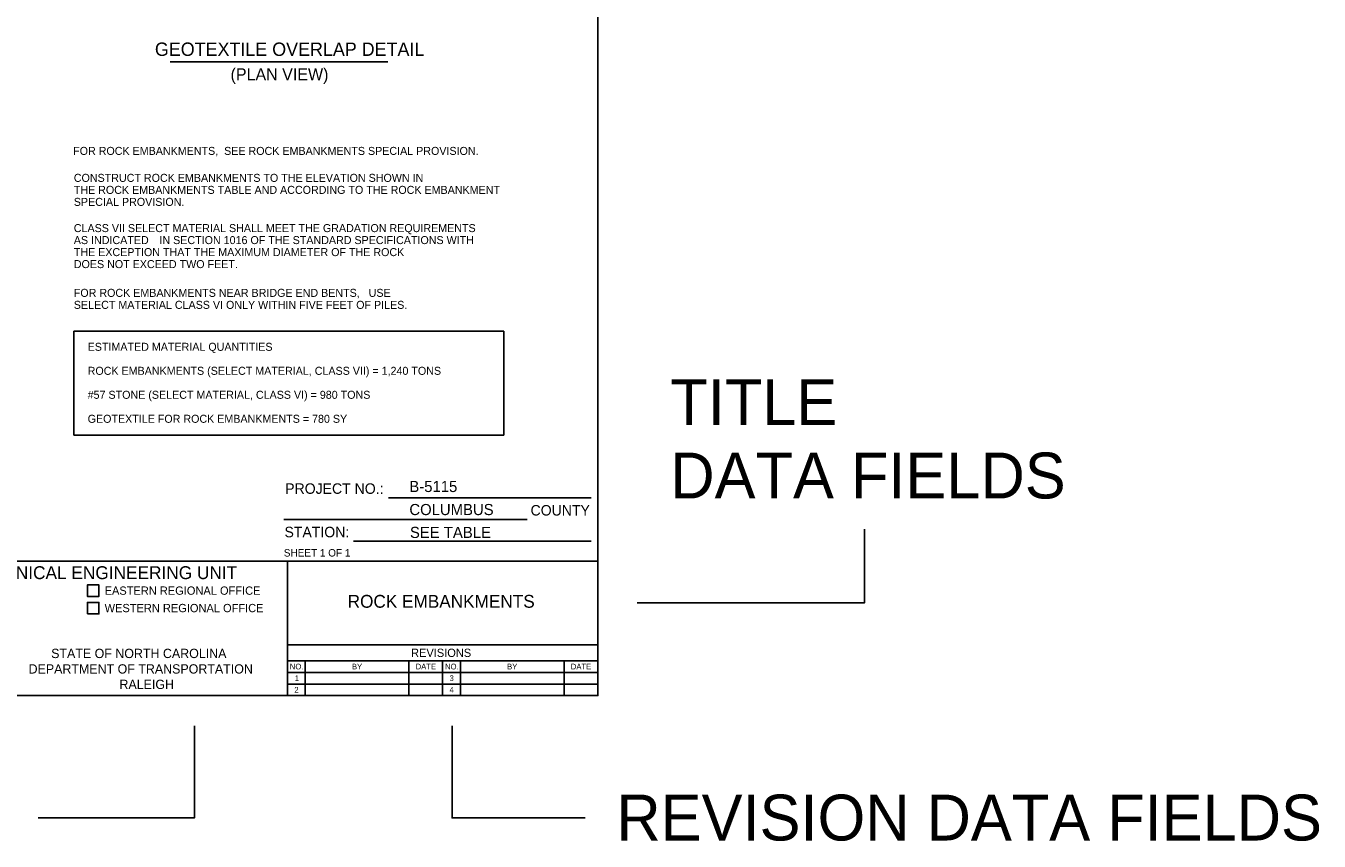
# Model space of a CAD drawing. Extents: x 2189223 to 2190097, y 563994 to 564498.
# Drawn here: x 2189702.6 to 2190097.3, y 563994.5 to 564243.4 of the extents above; entities that cross this region are included whole.
import ezdxf

# ---------------------------------------------------------------- set-up
doc = ezdxf.new("R2010")
doc.units = 0
for name, color, linetype in [('Default', 7, 'Continuous'), ('Geotech Sheets and Borders Cell', 7, 'Continuous'), ('Old_Level_2', 7, 'Continuous'), ('Old_Level_37', 7, 'Continuous')]:
    doc.layers.add(name, color=color, linetype=linetype)

msp = doc.modelspace()

# ---------------------------------------------------------------- linework, layer by layer
at = {"layer": 'Default'}
for points in [[(2189347.77, 564405.93), (2189877.15, 564405.93), (2189877.15, 564038.89), (2189347.77, 564038.89)], [(2189717.21, 564150.14), (2189848.44, 564150.14), (2189848.44, 564118.44), (2189717.21, 564118.44)]]:
    msp.add_lwpolyline(points, close=True, dxfattribs=at)
at = {"layer": 'Geotech Sheets and Borders Cell'}
for p, q in [((2189813.25, 564099.27), (2189875.1, 564099.27)), ((2189781.29, 564092.64), (2189855.53, 564092.64)), ((2189802.59, 564086.01), (2189875.1, 564086.01))]:
    msp.add_line(p, q, dxfattribs=at)
for points in [[(2189958.56, 564089.71), (2189958.56, 564067.26), (2189889.2, 564067.26)], [(2189754.02, 564029.63), (2189754.02, 564001.54), (2189706.34, 564001.54)], [(2189832.65, 564029.63), (2189832.65, 564001.54), (2189873.23, 564001.54)]]:
    msp.add_lwpolyline(points, dxfattribs=at)
for points in [[(2189667.83, 564079.96), (2189782.41, 564079.96), (2189782.41, 564038.89), (2189667.83, 564038.89)], [(2189782.41, 564079.96), (2189877.15, 564079.96), (2189877.15, 564054.38), (2189782.41, 564054.38)], [(2189782.41, 564079.96), (2189877.15, 564079.96), (2189877.15, 564038.89), (2189782.41, 564038.89)], [(2189721.36, 564069.19), (2189724.86, 564069.19), (2189724.86, 564072.69), (2189721.36, 564072.69)], [(2189721.36, 564063.85), (2189724.86, 564063.85), (2189724.86, 564067.35), (2189721.36, 564067.35)], [(2189782.41, 564054.38), (2189877.15, 564054.38), (2189877.15, 564049.53), (2189782.41, 564049.53)], [(2189782.41, 564054.38), (2189877.15, 564054.38), (2189877.15, 564038.89), (2189782.41, 564038.89)], [(2189782.41, 564049.53), (2189829.78, 564049.53), (2189829.78, 564038.89), (2189782.41, 564038.89)], [(2189782.41, 564049.53), (2189787.82, 564049.53), (2189787.82, 564045.98), (2189782.41, 564045.98)], [(2189787.82, 564049.53), (2189819.49, 564049.53), (2189819.49, 564045.98), (2189787.82, 564045.98)], [(2189819.49, 564049.53), (2189829.78, 564049.53), (2189829.78, 564045.98), (2189819.49, 564045.98)], [(2189829.78, 564049.53), (2189835.19, 564049.53), (2189835.19, 564045.98), (2189829.78, 564045.98)], [(2189829.78, 564049.53), (2189877.15, 564049.53), (2189877.15, 564038.89), (2189829.78, 564038.89)], [(2189835.19, 564049.53), (2189866.86, 564049.53), (2189866.86, 564045.98), (2189835.19, 564045.98)], [(2189866.86, 564049.53), (2189877.15, 564049.53), (2189877.15, 564045.98), (2189866.86, 564045.98)], [(2189782.41, 564045.98), (2189787.82, 564045.98), (2189787.82, 564042.43), (2189782.41, 564042.43)], [(2189787.82, 564045.98), (2189819.49, 564045.98), (2189819.49, 564042.43), (2189787.82, 564042.43)], [(2189819.49, 564045.98), (2189829.78, 564045.98), (2189829.78, 564042.43), (2189819.49, 564042.43)], [(2189829.78, 564045.98), (2189835.19, 564045.98), (2189835.19, 564042.43), (2189829.78, 564042.43)], [(2189835.19, 564045.98), (2189866.86, 564045.98), (2189866.86, 564042.43), (2189835.19, 564042.43)], [(2189866.86, 564045.98), (2189877.15, 564045.98), (2189877.15, 564042.43), (2189866.86, 564042.43)], [(2189782.41, 564042.43), (2189787.82, 564042.43), (2189787.82, 564038.89), (2189782.41, 564038.89)], [(2189787.82, 564042.43), (2189819.49, 564042.43), (2189819.49, 564038.89), (2189787.82, 564038.89)], [(2189819.49, 564042.43), (2189829.78, 564042.43), (2189829.78, 564038.89), (2189819.49, 564038.89)], [(2189829.78, 564042.43), (2189835.19, 564042.43), (2189835.19, 564038.89), (2189829.78, 564038.89)], [(2189835.19, 564042.43), (2189866.86, 564042.43), (2189866.86, 564038.89), (2189835.19, 564038.89)], [(2189866.86, 564042.43), (2189877.15, 564042.43), (2189877.15, 564038.89), (2189866.86, 564038.89)]]:
    msp.add_lwpolyline(points, close=True, dxfattribs=at)
at = {"layer": 'Old_Level_2'}
msp.add_line((2189813.05, 564232.34), (2189746.59, 564232.34), dxfattribs=at)
at = {"layer": 'Old_Level_37'}
msp.add_lwpolyline([(2189724.86, 564072.69), (2189721.36, 564072.69), (2189721.36, 564069.19), (2189724.86, 564069.19)], close=True, dxfattribs=at)
msp.add_lwpolyline([(2189724.86, 564072.69), (2189721.36, 564072.69), (2189721.36, 564069.19), (2189724.86, 564069.19)], close=True, dxfattribs=at)

# ---------------------------------------------------------------- texts
at = {"layer": 'Default'}
for s, height, p in [('GEOTEXTILE OVERLAP DETAIL', 4.0838, (2189741.95, 564234.2)), ('FOR ROCK EMBANKMENTS,  SEE ROCK EMBANKMENTS SPECIAL PROVISION.', 2.4419, (2189717, 564203.97)), ('CONSTRUCT ROCK EMBANKMENTS TO THE ELEVATION SHOWN IN ', 2.4419, (2189717.2, 564195.74)), ('THE ROCK EMBANKMENTS TABLE AND ACCORDING TO THE ROCK EMBANKMENT', 2.4419, (2189717.2, 564192.07)), ('SPECIAL PROVISION.', 2.4419, (2189717.2, 564188.41)), ('CLASS VII SELECT MATERIAL SHALL MEET THE GRADATION REQUIREMENTS ', 2.4419, (2189717.2, 564180.4)), ('AS INDICATED ', 2.4419, (2189717.2, 564176.74)), ('IN SECTION 1016 OF THE STANDARD SPECIFICATIONS WITH ', 2.4419, (2189743.35, 564176.74)), ('THE EXCEPTION THAT THE MAXIMUM DIAMETER OF THE ROCK ', 2.4419, (2189717.2, 564173.07)), ('DOES NOT EXCEED TWO FEET.', 2.4419, (2189717.2, 564169.41)), ('FOR ROCK EMBANKMENTS NEAR BRIDGE END BENTS,   USE', 2.4419, (2189717.2, 564160.63)), ('SELECT MATERIAL CLASS VI ONLY WITHIN FIVE FEET OF PILES.', 2.4419, (2189717.2, 564156.97)), ('ESTIMATED MATERIAL QUANTITIES', 2.4419, (2189721.43, 564144.16)), ('ROCK EMBANKMENTS (SELECT MATERIAL, CLASS VII) = 1,240 TONS', 2.4419, (2189721.43, 564136.83)), ('#57 STONE (SELECT MATERIAL, CLASS VI) = 980 TONS', 2.4419, (2189721.43, 564129.51)), ('GEOTEXTILE FOR ROCK EMBANKMENTS = 780 SY', 2.4419, (2189721.43, 564122.18))]:
    msp.add_text(s, height=height, dxfattribs=at).set_placement(p)
msp.add_text('(PLAN VIEW)', height=3.6568, rotation=360, dxfattribs=at).set_placement((2189765.04, 564226.75))
at = {"layer": 'Geotech Sheets and Borders Cell'}
for s, height, p in [('TITLE', 14, (2189899.27, 564121.49)), ('DATA FIELDS', 14, (2189899.27, 564099.09)), ('B-5115', 3.393, (2189819.62, 564101.04)), ('COLUMBUS', 3.393, (2189819.62, 564094)), ('SEE TABLE', 3.393, (2189819.8, 564087.02)), ('SHEET 1 OF 1', 2.2785, (2189781.3, 564081.34)), ('ROCK EMBANKMENTS', 3.92, (2189800.79, 564065.71)), ('NO.', 1.75, (2189783.14, 564046.88)), ('BY', 1.75, (2189802.09, 564046.88)), ('DATE', 1.75, (2189821.53, 564046.88)), ('NO.', 1.75, (2189830.51, 564046.88)), ('BY', 1.75, (2189849.46, 564046.88)), ('DATE', 1.75, (2189868.9, 564046.88)), ('2', 1.75, (2189784.52, 564039.79)), ('1', 1.75, (2189784.67, 564043.33)), ('4', 1.75, (2189831.88, 564039.79)), ('3', 1.75, (2189831.88, 564043.33)), ('REVISION DATA FIELDS', 14, (2189882.82, 563994.65))]:
    msp.add_text(s, height=height, dxfattribs=at).set_placement(p)
for s, height, p in [('PROJECT NO.:', 3.2042, (2189781.73, 564100.49)), ('COUNTY', 3.204, (2189856.62, 564093.86)), ('STATION:', 3.204, (2189781.51, 564087.23)), ('GEOTECHNICAL ENGINEERING UNIT', 3.9375, (2189673.46, 564074.45)), ('EASTERN REGIONAL OFFICE', 2.52, (2189726.61, 564069.68)), ('WESTERN REGIONAL OFFICE', 2.52, (2189726.61, 564064.36)), ('STATE OF NORTH CAROLINA', 2.835, (2189710.29, 564050.35)), ('REVISIONS', 2.52, (2189820.14, 564050.69)), ('DEPARTMENT OF TRANSPORTATION', 2.835, (2189703.4, 564045.62)), ('RALEIGH', 2.835, (2189731.14, 564040.9))]:
    msp.add_text(s, height=height, rotation=360, dxfattribs=at).set_placement(p)

doc.saveas('drawing.dxf')
